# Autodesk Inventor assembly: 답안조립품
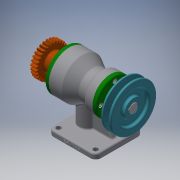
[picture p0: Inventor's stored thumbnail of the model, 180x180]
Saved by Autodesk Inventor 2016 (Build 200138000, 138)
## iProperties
Created: 2019-01
Part Number: 답안조립품
Material: 일반
Document SubType Name: Assembly
Designer: USER
Author: USER
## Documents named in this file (15)
- C:\Users\USER\Desktop\490107V1009\답안조립품.iam
- C:\Users\USER\Desktop\490107V1009\본체.ipt
- C:\Users\USER\Desktop\490107V1009\앞커버.ipt
- C:\Users\USER\Desktop\490107V1009\뒤커버.ipt
- C:\Users\USER\Desktop\490107V1009\베어링 6205.ipt
- C:\Users\USER\Desktop\490107V1009\베어링 6203.ipt
- C:\Users\USER\Desktop\490107V1009\축.ipt
- C:\Users\USER\Desktop\490107V1009\오일 실 25 38 8.ipt
- C:\Users\USER\Desktop\490107V1009\오일 실 17 30 8.ipt
- C:\Users\USER\Desktop\490107V1009\볼트 M4.ipt
- C:\Users\USER\Desktop\490107V1009\키 6 x 6 x 18.ipt
- C:\Users\USER\Desktop\490107V1009\스퍼기어.ipt
- C:\Users\USER\Desktop\490107V1009\멈춤나사 M3.ipt
- C:\Users\USER\Desktop\490107V1009\키 5 x 5 x 20.ipt
- C:\Users\USER\Desktop\490107V1009\V-벨트풀리.ipt
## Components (1 placed, 1 different names)
1. V-벨트풀리:1
